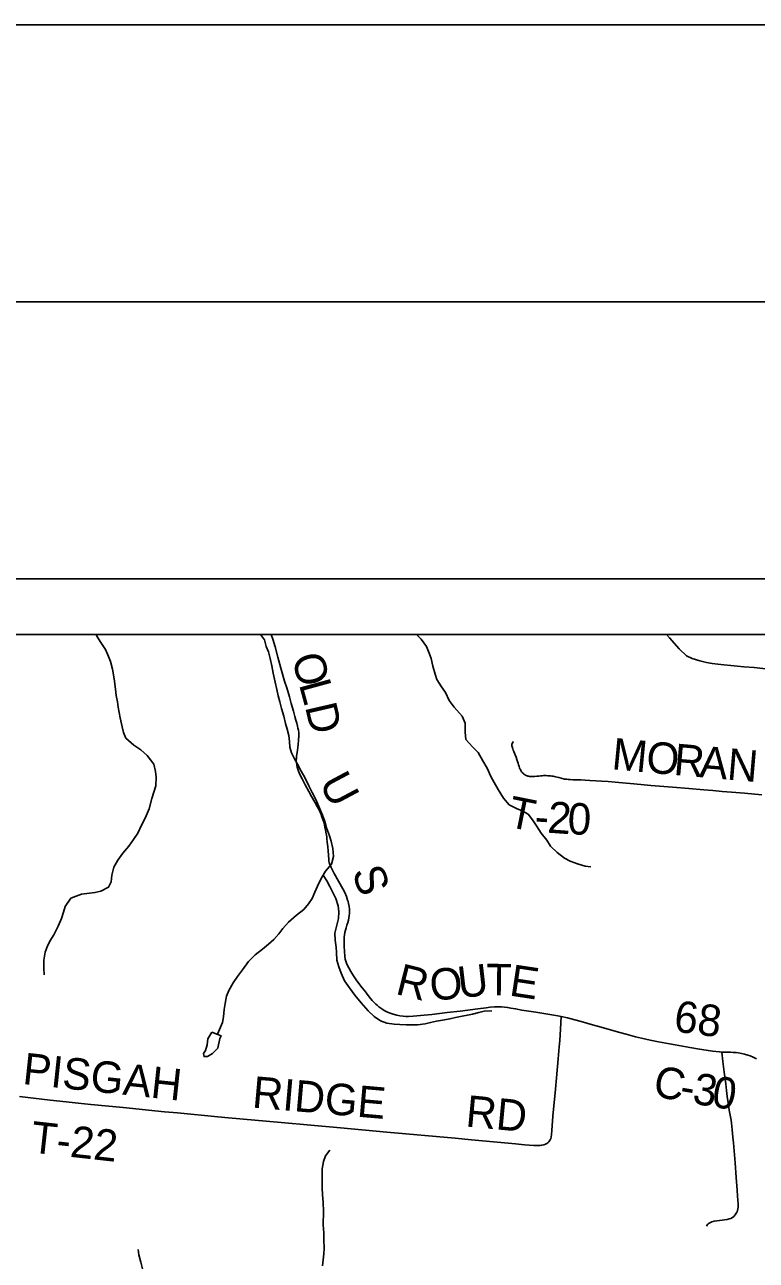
# Model space of a CAD drawing. Extents: x 0 to 34, y 0 to 22.
# Drawn here: x 3.312 to 4.632, y 19.77 to 22 of the extents above; entities that cross this region are included whole.
import ezdxf

# ---------------------------------------------------------------- set-up
doc = ezdxf.new("R2010")
doc.units = 0
for name, color, linetype in [('Default', 7, 'Continuous'), ('GM_X_County_Road', 7, 'Continuous'), ('GM_X_County_Road_Text', 7, 'Continuous'), ('GM_X_Minor_Lake', 7, 'Continuous'), ('GM_X_Minor_River', 7, 'Continuous'), ('GM_X_Township_Road', 7, 'Continuous'), ('GM_X_Township_Road_Text', 7, 'Continuous'), ('SH_Border', 7, 'Continuous'), ('SH_Cut_Line', 7, 'Continuous'), ('SH_Data', 7, 'Continuous')]:
    doc.layers.add(name, color=color, linetype=linetype)

msp = doc.modelspace()

# ---------------------------------------------------------------- linework, layer by layer
at = {"layer": 'Default'}
msp.add_lwpolyline([(8.6167, 20.8996), (2.3571, 20.8996), (2.3471, 20.8898), (2.3219, 20.8131), (2.3142, 20.7876), (2.3142, 19.0219)], dxfattribs=at)
at = {"layer": 'GM_X_County_Road'}
for points in [[(4.2801, 20.2096), (4.2741, 20.2108), (4.2342, 20.2174), (4.209, 20.2216), (4.1977, 20.2238), (4.1891, 20.2251), (4.1833, 20.2262), (4.1775, 20.227), (4.172, 20.2273), (4.1655, 20.2274), (4.1593, 20.2272), (4.1518, 20.2266), (4.1444, 20.2257), (4.1293, 20.2235), (4.0976, 20.2195), (4.0744, 20.217), (4.0465, 20.2135), (4.0258, 20.2116), (4.0129, 20.2105), (4.0045, 20.2101), (3.9997, 20.2101), (3.9948, 20.2105), (3.989, 20.211), (3.9833, 20.2121), (3.977, 20.2138), (3.9712, 20.2158), (3.9667, 20.2177), (3.9606, 20.2207), (3.9562, 20.2235), (3.9508, 20.2274), (3.9476, 20.2301), (3.9452, 20.2323), (3.9391, 20.239), (3.9336, 20.2455), (3.9287, 20.2519), (3.9249, 20.2568), (3.9211, 20.2618), (3.9112, 20.2745), (3.9051, 20.2831), (3.9003, 20.291), (3.8968, 20.2975), (3.8945, 20.3019), (3.8926, 20.3064), (3.8914, 20.3098), (3.8903, 20.3136), (3.8895, 20.3188), (3.8889, 20.3273), (3.8885, 20.3366), (3.8882, 20.3446), (3.8881, 20.3484), (3.8884, 20.3532), (3.8889, 20.3572), (3.8896, 20.3617), (3.8905, 20.3656), (3.8917, 20.37), (3.8932, 20.3746), (3.8948, 20.3797), (3.896, 20.384), (3.897, 20.3879), (3.8976, 20.3919), (3.898, 20.3956), (3.8982, 20.4001), (3.898, 20.4037), (3.8974, 20.4084), (3.8964, 20.414), (3.8955, 20.4172), (3.8946, 20.42), (3.8923, 20.4265), (3.8894, 20.4334), (3.8858, 20.4406), (3.8704, 20.4677), (3.8664, 20.4751), (3.8648, 20.4787), (3.8624, 20.484), (3.8617, 20.486), (3.8612, 20.4881), (3.8608, 20.4905), (3.8606, 20.4933), (3.8599, 20.5009), (3.8595, 20.5086), (3.8588, 20.5163), (3.8579, 20.5248), (3.8573, 20.5308), (3.8569, 20.5342), (3.8565, 20.5373), (3.8555, 20.5428), (3.8547, 20.5472), (3.8537, 20.5516), (3.8527, 20.5557), (3.8514, 20.5609), (3.85, 20.5653), (3.8482, 20.5705), (3.8467, 20.5747), (3.845, 20.5785), (3.8431, 20.5827), (3.8399, 20.5888), (3.8352, 20.597), (3.8296, 20.6068), (3.8245, 20.6159), (3.818, 20.6278), (3.8123, 20.6389), (3.8084, 20.6468), (3.8059, 20.6524), (3.8046, 20.656), (3.8036, 20.6597), (3.8028, 20.6639), (3.8023, 20.6676), (3.802, 20.6718), (3.8021, 20.6758), (3.8024, 20.6797), (3.8028, 20.6825), (3.8039, 20.6903), (3.8054, 20.7003), (3.8062, 20.7084), (3.8066, 20.7162), (3.8065, 20.7192), (3.8063, 20.722), (3.8057, 20.7264), (3.805, 20.7305), (3.8043, 20.7338), (3.8029, 20.7394), (3.8014, 20.7446), (3.7993, 20.7515), (3.7967, 20.7611), (3.7929, 20.7751), (3.7897, 20.7869), (3.7848, 20.8034), (3.7809, 20.8154), (3.7741, 20.8387), (3.7688, 20.8582), (3.7636, 20.8769), (3.7595, 20.8911), (3.7567, 20.8996)], [(4.5699, 20.1456), (4.5655, 20.1461), (4.5527, 20.1475), (4.5415, 20.149), (4.5297, 20.1507), (4.512, 20.1538), (4.4858, 20.1587), (4.4751, 20.1607), (4.4557, 20.1644), (4.4406, 20.1674), (4.4248, 20.1709), (4.4142, 20.1733), (4.3971, 20.1778), (4.3833, 20.1816), (4.3521, 20.1905), (4.3365, 20.1951), (4.3162, 20.2007), (4.3042, 20.2041), (4.291, 20.2073), (4.2801, 20.2096)], [(4.6321, 20.1333), (4.626, 20.1364), (4.6208, 20.1386), (4.6167, 20.14), (4.6107, 20.1417), (4.6027, 20.1434), (4.5989, 20.1441), (4.5953, 20.1446), (4.5899, 20.145), (4.5854, 20.1453), (4.5816, 20.1454), (4.5757, 20.1455), (4.5699, 20.1456)]]:
    msp.add_lwpolyline(points, dxfattribs=at)
at = {"layer": 'GM_X_Minor_Lake'}
for points in [[(3.6495, 20.1817), (3.6426, 20.1696), (3.6413, 20.159), (3.6381, 20.1485), (3.6343, 20.1432), (3.6357, 20.1375), (3.6418, 20.1374), (3.651, 20.143), (3.6602, 20.1527), (3.6642, 20.1701)], [(3.6642, 20.1701), (3.6662, 20.1752), (3.6495, 20.1817)]]:
    msp.add_lwpolyline(points, dxfattribs=at)
at = {"layer": 'GM_X_Minor_River'}
for points in [[(3.4409, 20.8996), (3.4419, 20.8966), (3.4493, 20.8851), (3.4578, 20.8721), (3.4622, 20.8626), (3.4669, 20.8507), (3.4705, 20.837), (3.4736, 20.8192), (3.4759, 20.8009), (3.4773, 20.7891), (3.4793, 20.7777), (3.4807, 20.7682), (3.4824, 20.7583), (3.4842, 20.7488), (3.4877, 20.7328), (3.4905, 20.7222), (3.4945, 20.7123), (3.5087, 20.6999), (3.5214, 20.691), (3.533, 20.6809), (3.5449, 20.6652), (3.5477, 20.6519), (3.5494, 20.6416), (3.5484, 20.6261), (3.5412, 20.6034), (3.5363, 20.5846), (3.5292, 20.5676), (3.523, 20.5552), (3.5163, 20.5405), (3.5085, 20.5296), (3.4996, 20.5176), (3.4892, 20.5045), (3.4803, 20.4921), (3.4725, 20.4793), (3.4689, 20.465), (3.4679, 20.4529), (3.4632, 20.4431), (3.4495, 20.4361), (3.4388, 20.4336), (3.429, 20.4322), (3.4146, 20.4309), (3.3955, 20.4236), (3.3847, 20.4083), (3.3822, 20.3981), (3.3786, 20.3867), (3.3724, 20.3728), (3.3645, 20.3574), (3.3575, 20.3461), (3.3528, 20.3355), (3.3489, 20.3257), (3.3464, 20.3114), (3.3465, 20.297), (3.3471, 20.2848)], [(3.7374, 20.8996), (3.7446, 20.8896), (3.7478, 20.8778), (3.7519, 20.8678), (3.7547, 20.8561), (3.758, 20.8431), (3.7605, 20.8294), (3.7637, 20.8135), (3.7666, 20.8002), (3.7691, 20.7884), (3.772, 20.7781), (3.7752, 20.7655), (3.7796, 20.7518), (3.7828, 20.7385), (3.7857, 20.7286), (3.7886, 20.7168), (3.79, 20.7062), (3.7906, 20.6963), (3.7935, 20.686), (3.7983, 20.6761), (3.8043, 20.6654), (3.8109, 20.6524), (3.8172, 20.6414), (3.8243, 20.6265), (3.8309, 20.6139), (3.8372, 20.6013), (3.8427, 20.5887), (3.849, 20.5734), (3.8534, 20.562), (3.8563, 20.5506), (3.8618, 20.5361), (3.8651, 20.5266), (3.8679, 20.5129), (3.8689, 20.4989), (3.8653, 20.4849), (3.8549, 20.4721), (3.8468, 20.459), (3.8405, 20.4454), (3.8355, 20.4345), (3.8308, 20.4231), (3.8242, 20.413), (3.8154, 20.4032), (3.8023, 20.3928), (3.7882, 20.3801), (3.7778, 20.3689), (3.7705, 20.3591), (3.7616, 20.349), (3.752, 20.3404), (3.7413, 20.3314), (3.7279, 20.321), (3.7156, 20.309), (3.7048, 20.2944), (3.6959, 20.2823), (3.6882, 20.2707), (3.6804, 20.2571), (3.6761, 20.2466), (3.6737, 20.2333), (3.6717, 20.2227), (3.6707, 20.2091), (3.6687, 20.1993), (3.6596, 20.1778)], [(4.0189, 20.8996), (4.0274, 20.8911), (4.0367, 20.8777), (4.0419, 20.8655), (4.0452, 20.856), (4.0484, 20.8423), (4.0524, 20.8278), (4.0557, 20.8179), (4.0642, 20.8049), (4.0713, 20.7946), (4.0779, 20.7801), (4.0869, 20.7682), (4.1015, 20.7521), (4.1066, 20.7395), (4.1064, 20.7229), (4.1081, 20.7099), (4.1201, 20.6965), (4.1298, 20.6861), (4.1384, 20.6716), (4.1462, 20.6579), (4.1532, 20.643), (4.1591, 20.6323), (4.1661, 20.6193), (4.1758, 20.604), (4.1863, 20.5917), (4.1995, 20.5851), (4.2096, 20.5808), (4.2206, 20.575), (4.2284, 20.5646), (4.2351, 20.5539), (4.244, 20.5405), (4.2541, 20.5283), (4.2604, 20.5176), (4.2724, 20.506), (4.2859, 20.4956), (4.2961, 20.4902), (4.3093, 20.4854), (4.3233, 20.4815), (4.3331, 20.4798)], [(4.4696, 20.8996), (4.4752, 20.8931), (4.4928, 20.8736), (4.5062, 20.8609), (4.5164, 20.8562), (4.53, 20.8518), (4.5421, 20.849), (4.5523, 20.847), (4.5622, 20.8457), (4.5731, 20.8444), (4.586, 20.8435), (4.5978, 20.8422), (4.6095, 20.8413), (4.6281, 20.8395), (4.6436, 20.8378), (4.6546, 20.8365), (4.6689, 20.8337), (4.6799, 20.8301), (4.6926, 20.8174), (4.7038, 20.8036), (4.7094, 20.7937)], [(3.8505, 20.465), (3.8573, 20.4546), (3.8625, 20.4447), (3.8673, 20.4348), (3.8732, 20.423), (3.8776, 20.4096), (3.8786, 20.399), (3.8781, 20.3865), (3.8745, 20.3725), (3.8717, 20.36), (3.8723, 20.3475), (3.874, 20.335), (3.8743, 20.3255), (3.8749, 20.3114), (3.8785, 20.2993), (3.8829, 20.2882), (3.8892, 20.2741), (3.8977, 20.2615), (3.9074, 20.2481), (3.919, 20.2346), (3.9317, 20.2204), (3.9422, 20.2097), (3.9539, 20.2019), (3.9656, 20.1976), (3.9784, 20.1963), (3.989, 20.1954), (4, 20.1949), (4.0103, 20.1947), (4.0205, 20.195), (4.0342, 20.1967), (4.0441, 20.1988), (4.0547, 20.2014), (4.0691, 20.2038), (4.079, 20.2056), (4.0893, 20.2081), (4.1011, 20.2102), (4.1106, 20.212), (4.1201, 20.2141), (4.1311, 20.217), (4.141, 20.2192), (4.1547, 20.2201)], [(3.849, 19.76), (3.8506, 19.7706), (3.8515, 19.7812), (3.852, 19.791), (3.8518, 19.8081), (3.8516, 19.8195), (3.8506, 19.8339), (3.851, 19.8582), (3.8504, 19.8749), (3.8494, 19.8878), (3.8488, 19.9007), (3.8486, 19.914), (3.8484, 19.9234), (3.8489, 19.9352), (3.851, 19.9484), (3.8545, 19.9583), (3.8626, 19.9688)], [(3.5164, 19.7895), (3.5178, 19.7796), (3.5213, 19.7666), (3.5263, 19.7472), (3.5299, 19.7346), (3.5331, 19.7205), (3.5359, 19.7065), (3.5379, 19.6928), (3.5392, 19.6825), (3.5428, 19.6688), (3.5479, 19.6547), (3.5627, 19.6394)]]:
    msp.add_lwpolyline(points, dxfattribs=at)
at = {"layer": 'GM_X_Township_Road'}
for points in [[(4.1931, 20.7062), (4.1924, 20.7046), (4.1915, 20.7027), (4.1911, 20.7006), (4.1911, 20.6982), (4.1918, 20.6955), (4.1921, 20.6944), (4.1925, 20.693), (4.1934, 20.6908), (4.1944, 20.688), (4.1971, 20.6819), (4.1985, 20.6781), (4.1999, 20.6736), (4.2012, 20.67), (4.2021, 20.6671), (4.2031, 20.6642), (4.204, 20.6614), (4.2048, 20.659), (4.2055, 20.6571), (4.2063, 20.6554), (4.2069, 20.6541), (4.2077, 20.6527), (4.2085, 20.6517), (4.2095, 20.6504), (4.2104, 20.6494), (4.2115, 20.6482), (4.2127, 20.6472), (4.2139, 20.6464), (4.2154, 20.6455), (4.2167, 20.6449), (4.2182, 20.6442), (4.2195, 20.6437), (4.2211, 20.6434), (4.2225, 20.6431), (4.2244, 20.643), (4.2263, 20.6429), (4.2289, 20.6429), (4.2316, 20.643), (4.2361, 20.6435), (4.2393, 20.6439), (4.2428, 20.6443), (4.2458, 20.6445), (4.2481, 20.6447), (4.2504, 20.6448), (4.2529, 20.6447), (4.2556, 20.6445), (4.2583, 20.6444), (4.2608, 20.6441), (4.2631, 20.6439), (4.2652, 20.6435), (4.2672, 20.6432), (4.2697, 20.6426), (4.2724, 20.6419), (4.2756, 20.641), (4.2797, 20.6398), (4.2817, 20.6393), (4.2842, 20.6388), (4.286, 20.6385), (4.288, 20.6383), (4.2899, 20.6381), (4.2925, 20.6379), (4.2959, 20.6376), (4.3006, 20.6373), (4.3052, 20.6371), (4.3099, 20.637), (4.3156, 20.6368), (4.3232, 20.6365), (4.3313, 20.6361), (4.3421, 20.6355), (4.3525, 20.6347), (4.3644, 20.6338), (4.3773, 20.6328), (4.3906, 20.6317), (4.4109, 20.6298), (4.4295, 20.628), (4.4419, 20.6268), (4.4574, 20.6255), (4.4804, 20.6236), (4.5104, 20.6213), (4.5374, 20.6189), (4.5536, 20.6176), (4.57, 20.6162), (4.5874, 20.6147), (4.6103, 20.6127), (4.642, 20.6102)], [(3.3026, 20.0655), (3.3581, 20.059), (3.3868, 20.0556), (3.4083, 20.0535), (3.4314, 20.0513), (3.4897, 20.0454), (3.5645, 20.0381), (3.5878, 20.0358), (3.6603, 20.0288), (3.6794, 20.027), (3.7746, 20.0188), (3.8815, 20.0092), (3.9655, 20.001), (4.0884, 19.9902), (4.1183, 19.9874), (4.1977, 19.9799), (4.2137, 19.9784), (4.2308, 19.9771), (4.2385, 19.9769), (4.2419, 19.9771), (4.2444, 19.9774), (4.2483, 19.9784), (4.2515, 19.9794), (4.254, 19.9808), (4.2559, 19.9821), (4.2574, 19.9836), (4.2587, 19.9853), (4.26, 19.9873), (4.2609, 19.9894), (4.2616, 19.9922), (4.2623, 19.9971), (4.2628, 20.0041), (4.2649, 20.0301), (4.2695, 20.0785), (4.2714, 20.0992), (4.2746, 20.1334), (4.2765, 20.1551), (4.2774, 20.1668), (4.2787, 20.1872), (4.2801, 20.2096)], [(4.542, 19.8316), (4.5436, 19.8342), (4.5449, 19.8356), (4.5468, 19.8371), (4.549, 19.8383), (4.5519, 19.8393), (4.5561, 19.8403), (4.5654, 19.8417), (4.5795, 19.8436), (4.5831, 19.8444), (4.5861, 19.8454), (4.5888, 19.8469), (4.5912, 19.8488), (4.5936, 19.8516), (4.5957, 19.8547), (4.5971, 19.8575), (4.5979, 19.8599), (4.5986, 19.8629), (4.5989, 19.866), (4.5989, 19.8709), (4.598, 19.8858), (4.5973, 19.8963), (4.5957, 19.9192), (4.594, 19.9459), (4.5919, 19.9674), (4.5906, 19.9816), (4.5897, 19.9921), (4.5885, 20.0051), (4.5872, 20.0174), (4.5864, 20.023), (4.5849, 20.0315), (4.5832, 20.0406), (4.5815, 20.0504), (4.5793, 20.0657), (4.5781, 20.0762), (4.5767, 20.0885), (4.5758, 20.0965), (4.5752, 20.1008), (4.5742, 20.1094), (4.5717, 20.1285), (4.5699, 20.1456)]]:
    msp.add_lwpolyline(points, dxfattribs=at)
at = {"layer": 'SH_Border'}
msp.add_lwpolyline([(1.5, 21.5), (33.5, 21.5), (33.5, 0.5), (1.5, 0.5)], close=True, dxfattribs=at)
at = {"layer": 'SH_Cut_Line'}
msp.add_lwpolyline([(0, 0), (34, 0), (34, 22), (0, 22)], close=True, dxfattribs=at)
msp.add_lwpolyline([(9.1142, 20.8996), (2.3142, 20.8996), (2.3142, 19.0219)], dxfattribs=at)
at = {"layer": 'SH_Data'}
for p, q in [((2.2142, 20.9996), (9.2142, 20.9996)), ((2.3142, 20.8996), (9.1142, 20.8996))]:
    msp.add_line(p, q, dxfattribs=at)

# ---------------------------------------------------------------- texts
at = {"layer": 'GM_X_County_Road_Text'}
for s, height, rotation, p in [('O', 0.0568, 285.3117, (3.7932, 20.858)), ('L', 0.0568, 285.2831, (3.8064, 20.8098)), ('D', 0.0568, 283.0608, (3.8175, 20.7693)), ('U', 0.0568, 298.086, (3.8421, 20.6318)), ('S', 0.0568, 288.8245, (3.902, 20.4715)), ('R', 0.0568, 345.7943, (3.979, 20.2511)), ('O', 0.0568, 5.2528, (4.0452, 20.238)), ('U', 0.0568, 6.6358, (4.0964, 20.2427)), ('T', 0.0568, 359.2993, (4.1442, 20.2484)), ('E', 0.0568, 351.3532, (4.1846, 20.248)), ('68', 0.05682, 352.4495, (4.4813, 20.1832)), ('C', 0.0568, 347.7631, (4.443, 20.0675)), ('3', 0.0568, 350.6861, (4.5148, 20.0531)), ('0', 0.0568, 350.8369, (4.5495, 20.0474)), ('-', 0.0568, 350.438, (4.4915, 20.057))]:
    msp.add_text(s, height=height, rotation=rotation, dxfattribs=at).set_placement(p)
at = {"layer": 'GM_X_Township_Road_Text'}
for s, height, rotation, p in [('M', 0.0568, 354.4919, (4.3697, 20.6564)), ('O', 0.0568, 355.057, (4.4317, 20.6504)), ('R', 0.0568, 355.0566, (4.4815, 20.6461)), ('A', 0.0568, 355.0561, (4.528, 20.6421)), ('N', 0.0568, 355.0542, (4.5778, 20.6377)), ('T', 0.0568, 348.6022, (4.181, 20.5528)), ('2', 0.0568, 355.8905, (4.254, 20.5418)), ('0', 0.0568, 357.3604, (4.2905, 20.5392)), ('-', 0.0568, 356.1939, (4.2308, 20.5433)), ('PISGAH', 0.05682, 353.9305, (3.3068, 20.0882)), ('RIDGE', 0.05682, 355.0206, (3.7211, 20.0457)), ('RD', 0.05682, 354.5859, (4.1061, 20.0115)), ('T-22', 0.05682, 353.6641, (3.3211, 19.9647))]:
    msp.add_text(s, height=height, rotation=rotation, dxfattribs=at).set_placement(p)

doc.saveas('drawing.dxf')
